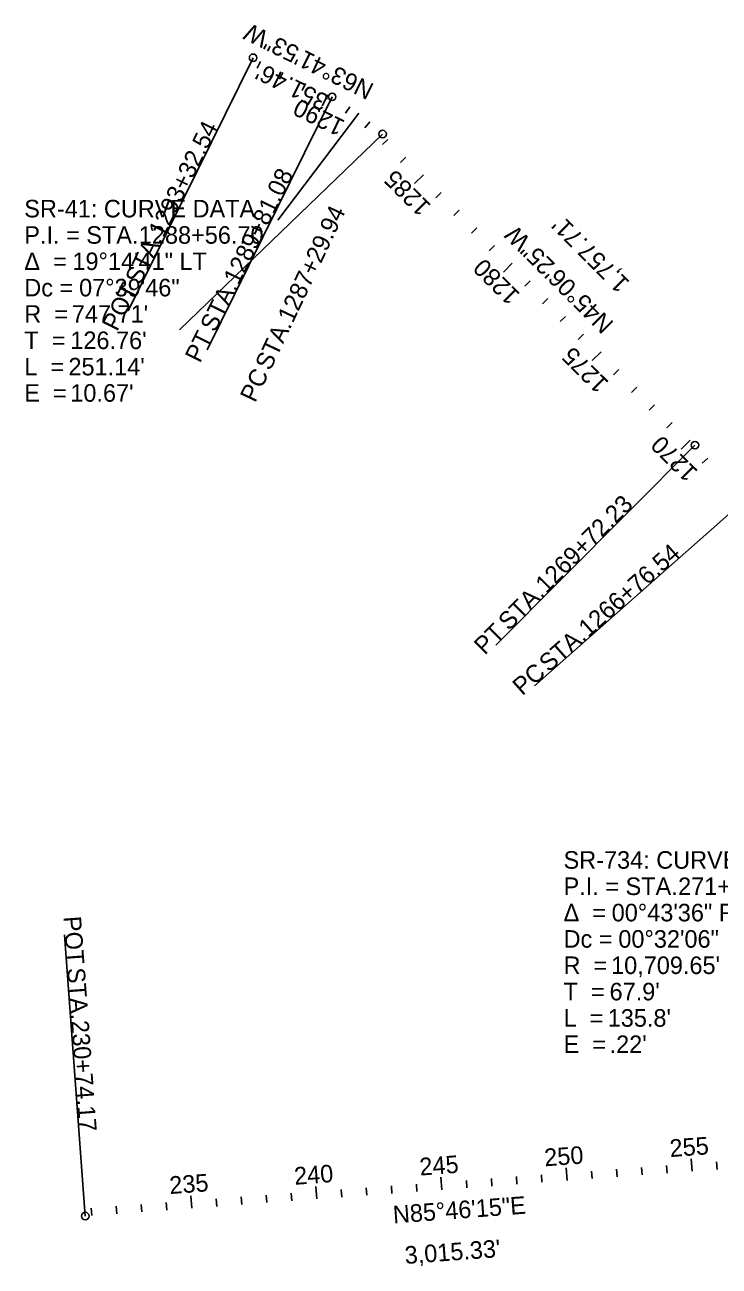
# Model space of a CAD drawing. Extents: x 99589 to 110840, y 526591 to 533644.
# Drawn here: x 99589 to 102357, y 528438 to 533388 of the extents above; entities that cross this region are included whole.
import ezdxf

# ---------------------------------------------------------------- set-up
doc = ezdxf.new("R2010")
doc.units = 0
for name, color, linetype in [('GE_P_Alignment_500_Bearings', 7, 'Continuous'), ('GE_P_Alignment_500_Cardinal_Points', 7, 'Continuous'), ('GE_P_Alignment_500_Curve_Data', 7, 'Continuous'), ('GE_P_Alignment_500_Distances', 7, 'Continuous'), ('GE_P_Alignment_500_Stations', 7, 'Continuous')]:
    doc.layers.add(name, color=color, linetype=linetype)

msp = doc.modelspace()

# ---------------------------------------------------------------- linework, layer by layer
at = {"layer": 'GE_P_Alignment_500_Cardinal_Points'}
for p, q in [((100498.9, 533257), (100000.4, 532248.4)), ((100814, 533101.2), (100315.5, 532092.7)), ((101015.2, 532952.9), (100205.9, 532171.6)), ((102260.4, 531712.4), (101466.4, 530915.4)), ((102463.2, 531497.2), (101620.2, 530752.1)), ((99829.8, 528638.2), (99746.8, 529760.2))]:
    msp.add_line(p, q, dxfattribs=at)
for centre in [(100498.9, 533257), (100814, 533101.2), (101015.2, 532952.9), (102260.4, 531712.4), (99829.8, 528638.2)]:
    msp.add_circle(centre, 15, dxfattribs=at)
at = {"layer": 'GE_P_Alignment_500_Curve_Data'}
msp.add_line((100919.9, 533036.3), (100597.8, 532609.2), dxfattribs=at)
at = {"layer": 'GE_P_Alignment_500_Stations'}
for p, q in [((100528.1, 533242.5), (100514.8, 533215.6)), ((100617.7, 533198.2), (100604.5, 533171.3)), ((100707.4, 533153.9), (100694.1, 533127)), ((100797, 533109.6), (100774.9, 533064.8)), ((100884.3, 533060.9), (100867.9, 533035.7)), ((100964.3, 533001), (100944.7, 532978.2)), ((101036.4, 532931.8), (101015.3, 532910.6)), ((101107.3, 532861.2), (101086.1, 532840)), ((101178.1, 532790.7), (101142.8, 532755.2)), ((101249, 532720.1), (101227.8, 532698.8)), ((101319.8, 532649.5), (101298.6, 532628.2)), ((101390.7, 532578.9), (101369.5, 532557.7)), ((101461.5, 532508.3), (101440.3, 532487.1)), ((101532.3, 532437.8), (101497, 532402.3)), ((101603.2, 532367.2), (101582, 532345.9)), ((101674, 532296.6), (101652.8, 532275.3)), ((101744.9, 532226), (101723.7, 532204.8)), ((101815.7, 532155.4), (101794.5, 532134.2)), ((101886.6, 532084.9), (101851.3, 532049.4)), ((101957.4, 532014.3), (101936.2, 531993)), ((102028.2, 531943.7), (102007.1, 531922.5)), ((102099.1, 531873.1), (102077.9, 531851.9)), ((102169.9, 531802.5), (102148.7, 531781.3)), ((102240.8, 531732), (102205.5, 531696.5)), ((102311.2, 531661), (102289.7, 531640.1)), ((102249, 528817.1), (102245.3, 528867)), ((101750.4, 528780.3), (101746.7, 528830.1)), ((101850.1, 528787.6), (101847.9, 528817.5)), ((101949.8, 528795), (101947.6, 528824.9)), ((102049.6, 528802.4), (102047.3, 528832.3)), ((102149.3, 528809.8), (102147.1, 528839.7)), ((102348.7, 528824.5), (102346.5, 528854.4)), ((101152, 528736), (101149.8, 528765.9)), ((101251.7, 528743.4), (101248, 528793.2)), ((101351.5, 528750.8), (101349.3, 528780.7)), ((101451.2, 528758.1), (101449, 528788)), ((101550.9, 528765.5), (101548.7, 528795.4)), ((101650.6, 528772.9), (101648.4, 528802.8)), ((100254.5, 528669.6), (100250.8, 528719.5)), ((100453.9, 528684.4), (100451.7, 528714.3)), ((100553.6, 528691.8), (100551.4, 528721.7)), ((100653.4, 528699.1), (100651.2, 528729)), ((100753.1, 528706.5), (100749.4, 528756.4)), ((100852.8, 528713.9), (100850.6, 528743.8)), ((100952.6, 528721.3), (100950.3, 528751.2)), ((101052.3, 528728.6), (101050.1, 528758.5)), ((99855.5, 528640.1), (99853.3, 528670.1)), ((99955.3, 528647.5), (99953.1, 528677.4)), ((100055, 528654.9), (100052.8, 528684.8)), ((100154.7, 528662.3), (100152.5, 528692.2)), ((100354.2, 528677), (100352, 528706.9))]:
    msp.add_line(p, q, dxfattribs=at)

# ---------------------------------------------------------------- texts
at = {"layer": 'GE_P_Alignment_500_Bearings'}
for s, rotation, p in [('N63°41\'53"W', 153.6979, (100985.6, 533150.2)), ('N45°06\'25"W', 135.1069, (101940.6, 532200.4)), ('N85°46\'15"E', 4.2292, (101058.9, 528608.8))]:
    msp.add_text(s, height=70, rotation=rotation, dxfattribs=at).set_placement(p)
at = {"layer": 'GE_P_Alignment_500_Cardinal_Points'}
for s, rotation, p in [('1293+32.54', 63.6979, (100141.4, 532536)), ('1289+81.08', 63.6979, (100440.4, 532347.6)), ('1287+29.94', 64.7452, (100657, 532196)), (' STA. ', 63.6979, (100036.7, 532324.2)), ('POT', 63.6979, (99956.9, 532162.8)), (' STA. ', 63.6979, (100335.7, 532135.8)), (' STA. ', 64.7452, (100556.2, 531982.3)), ('PT', 63.6979, (100286.8, 532036.9)), ('PC', 64.7452, (100507.3, 531878.6)), ('1269+72.23', 45.1069, (101667.1, 531118.4)), ('1266+76.54', 41.4739, (101835, 530943.4)), (' STA. ', 45.1069, (101500.4, 530951)), ('PT', 45.1069, (101422.5, 530872.8)), (' STA. ', 41.4739, (101658, 530786.9)), ('PC', 41.4739, (101572.1, 530711)), ('POT', 274.2292, (99742.6, 529831.8)), (' STA. ', 274.2292, (99755.9, 529652.2)), ('230+74.17', 274.2292, (99773.3, 529416.6))]:
    msp.add_text(s, height=70, rotation=rotation, dxfattribs=at).set_placement(p)
at = {"layer": 'GE_P_Alignment_500_Curve_Data'}
for s, p in [('SR-41: CURVE DATA', (99586.7, 532620.5)), ('P.I. = STA. ', (99586.7, 532515.5)), ('1288+56.70', (100043.4, 532515.5)), ('Δ  = ', (99586.7, 532410.5)), ('19°14\'41" LT', (99778.6, 532410.5)), ('07°39\'46"', (99805.2, 532305.5)), ('Dc = ', (99586.7, 532305.5)), ('R  = ', (99586.7, 532200.5)), ("747.71'", (99776.3, 532200.5)), ('T  = ', (99586.7, 532095.5)), ("126.76'", (99770.2, 532095.5)), ('L  = ', (99586.7, 531990.5)), ("251.14'", (99762.7, 531990.5)), ('E  = ', (99586.7, 531885.5)), ("10.67'", (99770.2, 531885.5)), ('SR-734: CURVE DATA', (101736.7, 530023.3)), ('P.I. = STA. ', (101736.7, 529918.3)), ('271+59.39', (102193.3, 529918.3)), ('Δ  = ', (101736.7, 529813.3)), ('00°43\'36" RT', (101928.6, 529813.3)), ('Dc = ', (101736.7, 529708.3)), ('00°32\'06"', (101955.1, 529708.3)), ('R  = ', (101736.7, 529603.3)), ("10,709.65'", (101926.2, 529603.3)), ('T  = ', (101736.7, 529498.3)), ("67.9'", (101920.1, 529498.3)), ('L  = ', (101736.7, 529393.3)), ("135.8'", (101912.7, 529393.3)), ('E  = ', (101736.7, 529288.3)), (".22'", (101920.2, 529288.3))]:
    msp.add_text(s, height=70, dxfattribs=at).set_placement(p)
at = {"layer": 'GE_P_Alignment_500_Distances'}
for s, rotation, p in [("351.46'", 153.6979, (100805.7, 533104.2)), ("1,757.71'", 135.1069, (102004, 532362.3)), ("3,015.33'", 4.2292, (101105.9, 528446.9))]:
    msp.add_text(s, height=70, rotation=rotation, dxfattribs=at).set_placement(p)
at = {"layer": 'GE_P_Alignment_500_Stations'}
for s, rotation, p in [('1290', 153.6979, (100869.4, 533004.1)), ('1285', 135.1069, (101212.3, 532668.3)), ('1280', 135.1069, (101567.3, 532314.7)), ('1275', 135.1069, (101920.8, 531962.6)), ('1270', 135.1069, (102275.7, 531608.9)), ('250', 4.2292, (101662.3, 528836.4)), ('255', 4.2292, (102162, 528873.4)), ('245', 4.2292, (101164.7, 528799.6)), ('240', 4.2292, (100665, 528762.7)), ('235', 4.2292, (100167.5, 528725.9))]:
    msp.add_text(s, height=70, rotation=rotation, dxfattribs=at).set_placement(p)

doc.saveas('drawing.dxf')
